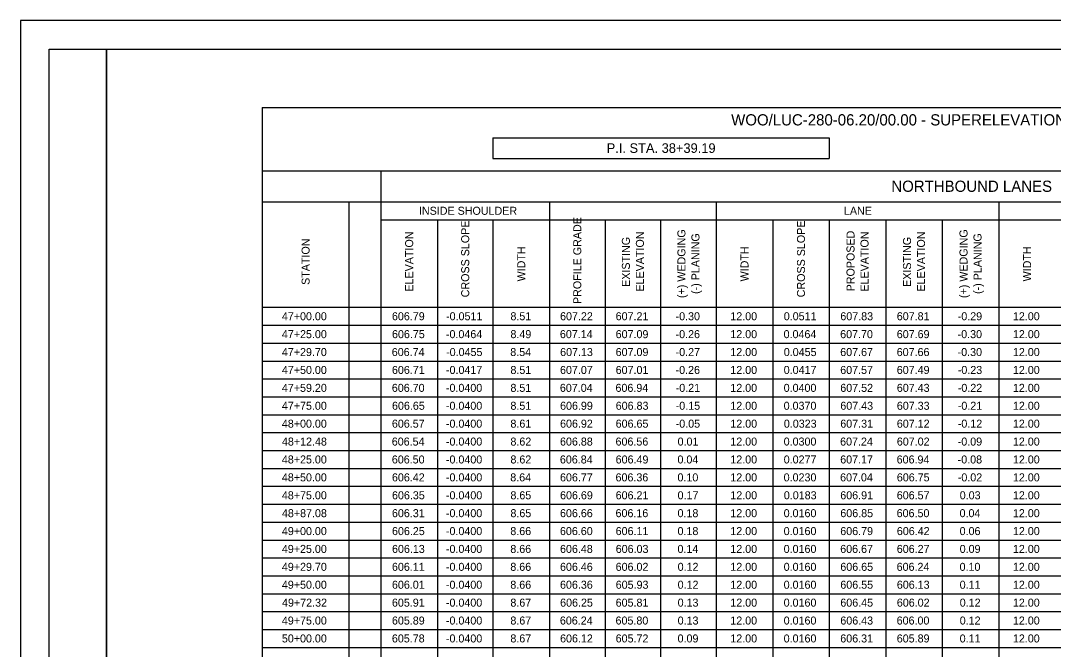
# Model space of a CAD drawing. Extents: x 0 to 34, y 0 to 22.
# Drawn here: x 0 to 18.06, y 11.01 to 22 of the extents above; entities that cross this region are included whole.
import ezdxf

# ---------------------------------------------------------------- set-up
doc = ezdxf.new("R2010")
doc.units = 0
for name, color, linetype in [('Default', 7, 'Continuous'), ('SH_Border', 7, 'Continuous'), ('SH_Cut_Line', 7, 'Continuous')]:
    doc.layers.add(name, color=color, linetype=linetype)

msp = doc.modelspace()

# ---------------------------------------------------------------- linework, layer by layer
at = {"layer": 'Default'}
for p, q in [((4.225, 20.48), (29.277, 20.48)), ((4.225, 20.48), (4.225, 1.522)), ((8.26, 19.953), (14.14, 19.953)), ((8.26, 19.953), (8.26, 19.591)), ((14.14, 19.953), (14.14, 19.591)), ((8.26, 19.591), (14.14, 19.591)), ((4.225, 19.376), (29.277, 19.376)), ((6.3, 19.376), (6.3, 1.522)), ((4.225, 18.833), (29.277, 18.833)), ((5.74, 18.833), (5.74, 1.522)), ((9.249, 18.833), (9.249, 1.522)), ((12.164, 18.833), (12.164, 1.522)), ((17.105, 18.833), (17.105, 1.522)), ((6.3, 18.52), (26.938, 18.52)), ((7.289, 18.52), (7.289, 1.522)), ((8.26, 18.52), (8.26, 1.522)), ((10.22, 18.52), (10.22, 1.522)), ((11.192, 18.52), (11.192, 1.522)), ((13.152, 18.52), (13.152, 1.522)), ((14.14, 18.52), (14.14, 1.522)), ((15.129, 18.52), (15.129, 1.522)), ((16.117, 18.52), (16.117, 1.522)), ((4.225, 16.988), (29.277, 16.988)), ((4.225, 16.675), (29.277, 16.675)), ((4.225, 16.362), (29.277, 16.362)), ((4.225, 16.049), (29.277, 16.049)), ((4.225, 15.736), (29.277, 15.736)), ((4.225, 15.424), (29.277, 15.424)), ((4.225, 15.111), (29.277, 15.111)), ((4.225, 14.798), (29.277, 14.798)), ((4.225, 14.485), (29.277, 14.485)), ((4.225, 14.172), (29.277, 14.172)), ((4.225, 13.859), (29.277, 13.859)), ((4.225, 13.546), (29.277, 13.546)), ((4.225, 13.233), (29.277, 13.233)), ((4.225, 12.92), (29.277, 12.92)), ((4.225, 12.607), (29.277, 12.607)), ((4.225, 12.294), (29.277, 12.294)), ((4.225, 11.981), (29.277, 11.981)), ((4.225, 11.668), (29.277, 11.668)), ((4.225, 11.355), (29.277, 11.355)), ((4.225, 11.042), (29.277, 11.042))]:
    msp.add_line(p, q, dxfattribs=at)
at = {"layer": 'SH_Border'}
for points in [[(0.5, 21.5), (1.5, 21.5), (1.5, 0.5), (0.5, 0.5)], [(1.5, 21.5), (33.5, 21.5), (33.5, 0.5), (1.5, 0.5)]]:
    msp.add_lwpolyline(points, close=True, dxfattribs=at)
at = {"layer": 'SH_Cut_Line'}
msp.add_lwpolyline([(0, 0), (34, 0), (34, 22), (0, 22)], close=True, dxfattribs=at)

# ---------------------------------------------------------------- texts
at = {"layer": 'Default'}
for s, height, p in [('WOO/LUC-280-06.20/00.00 - SUPERELEVATION TABLE', 0.196, (12.425, 20.168)), ('P.I. STA. 38+39.19', 0.168, (10.248, 19.688)), ('NORTHBOUND LANES', 0.196, (15.226, 19.007)), ('INSIDE SHOULDER', 0.14, (6.965, 18.606)), ('LANE', 0.14, (14.397, 18.606)), ('47+00.00', 0.14, (4.568, 16.762)), ('606.79', 0.14, (6.493, 16.762)), ('-0.0511', 0.14, (7.439, 16.762)), ('8.51', 0.14, (8.565, 16.762)), ('607.22', 0.14, (9.433, 16.762)), ('607.21', 0.14, (10.405, 16.762)), ('-0.30', 0.14, (11.453, 16.762)), ('12.00', 0.14, (12.41, 16.762)), ('0.0511', 0.14, (13.345, 16.762)), ('607.83', 0.14, (14.334, 16.762)), ('607.81', 0.14, (15.321, 16.762)), ('-0.29', 0.14, (16.387, 16.762)), ('12.00', 0.14, (17.352, 16.762)), ('47+25.00', 0.14, (4.568, 16.449)), ('606.75', 0.14, (6.494, 16.449)), ('-0.0464', 0.14, (7.437, 16.449)), ('8.49', 0.14, (8.565, 16.449)), ('607.14', 0.14, (9.43, 16.449)), ('607.09', 0.14, (10.405, 16.449)), ('-0.26', 0.14, (11.453, 16.449)), ('12.00', 0.14, (12.41, 16.449)), ('0.0464', 0.14, (13.342, 16.449)), ('607.70', 0.14, (14.331, 16.449)), ('607.69', 0.14, (15.321, 16.449)), ('-0.30', 0.14, (16.385, 16.449)), ('12.00', 0.14, (17.352, 16.449)), ('47+29.70', 0.14, (4.568, 16.136)), ('606.74', 0.14, (6.49, 16.136)), ('-0.0455', 0.14, (7.44, 16.136)), ('8.54', 0.14, (8.562, 16.136)), ('607.13', 0.14, (9.434, 16.136)), ('607.09', 0.14, (10.405, 16.136)), ('-0.27', 0.14, (11.454, 16.136)), ('12.00', 0.14, (12.41, 16.136)), ('0.0455', 0.14, (13.345, 16.136)), ('607.67', 0.14, (14.332, 16.136)), ('607.66', 0.14, (15.32, 16.136)), ('-0.30', 0.14, (16.385, 16.136)), ('12.00', 0.14, (17.352, 16.136)), ('47+50.00', 0.14, (4.568, 15.823)), ('606.71', 0.14, (6.493, 15.823)), ('-0.0417', 0.14, (7.438, 15.823)), ('8.51', 0.14, (8.565, 15.823)), ('607.07', 0.14, (9.432, 15.823)), ('607.01', 0.14, (10.405, 15.823)), ('-0.26', 0.14, (11.453, 15.823)), ('12.00', 0.14, (12.41, 15.823)), ('0.0417', 0.14, (13.344, 15.823)), ('607.57', 0.14, (14.332, 15.823)), ('607.49', 0.14, (15.321, 15.823)), ('-0.23', 0.14, (16.388, 15.823)), ('12.00', 0.14, (17.352, 15.823)), ('47+59.20', 0.14, (4.568, 15.51)), ('606.70', 0.14, (6.491, 15.51)), ('-0.0400', 0.14, (7.437, 15.51)), ('8.51', 0.14, (8.565, 15.51)), ('607.04', 0.14, (9.43, 15.51)), ('606.94', 0.14, (10.402, 15.51)), ('-0.21', 0.14, (11.455, 15.51)), ('12.00', 0.14, (12.41, 15.51)), ('0.0400', 0.14, (13.343, 15.51)), ('607.52', 0.14, (14.333, 15.51)), ('607.43', 0.14, (15.322, 15.51)), ('-0.22', 0.14, (16.388, 15.51)), ('12.00', 0.14, (17.352, 15.51)), ('47+75.00', 0.14, (4.568, 15.197)), ('606.65', 0.14, (6.494, 15.197)), ('-0.0400', 0.14, (7.437, 15.197)), ('8.51', 0.14, (8.565, 15.197)), ('606.99', 0.14, (9.433, 15.197)), ('606.83', 0.14, (10.406, 15.197)), ('-0.15', 0.14, (11.455, 15.197)), ('12.00', 0.14, (12.41, 15.197)), ('0.0370', 0.14, (13.343, 15.197)), ('607.43', 0.14, (14.334, 15.197)), ('607.33', 0.14, (15.322, 15.197)), ('-0.21', 0.14, (16.388, 15.197)), ('12.00', 0.14, (17.352, 15.197)), ('48+00.00', 0.14, (4.568, 14.884)), ('606.57', 0.14, (6.492, 14.884)), ('-0.0400', 0.14, (7.437, 14.884)), ('8.61', 0.14, (8.565, 14.884)), ('606.92', 0.14, (9.433, 14.884)), ('606.65', 0.14, (10.405, 14.884)), ('-0.05', 0.14, (11.455, 14.884)), ('12.00', 0.14, (12.41, 14.884)), ('0.0323', 0.14, (13.346, 14.884)), ('607.31', 0.14, (14.333, 14.884)), ('607.12', 0.14, (15.322, 14.884)), ('-0.12', 0.14, (16.388, 14.884)), ('12.00', 0.14, (17.352, 14.884)), ('48+12.48', 0.14, (4.569, 14.571)), ('606.54', 0.14, (6.49, 14.571)), ('-0.0400', 0.14, (7.437, 14.571)), ('8.62', 0.14, (8.565, 14.571)), ('606.88', 0.14, (9.432, 14.571)), ('606.56', 0.14, (10.403, 14.571)), ('0.01', 0.14, (11.488, 14.571)), ('12.00', 0.14, (12.41, 14.571)), ('0.0300', 0.14, (13.343, 14.571)), ('607.24', 0.14, (14.33, 14.571)), ('607.02', 0.14, (15.322, 14.571)), ('-0.09', 0.14, (16.387, 14.571)), ('12.00', 0.14, (17.352, 14.571)), ('48+25.00', 0.14, (4.568, 14.258)), ('606.50', 0.14, (6.491, 14.258)), ('-0.0400', 0.14, (7.437, 14.258)), ('8.62', 0.14, (8.565, 14.258)), ('606.84', 0.14, (9.43, 14.258)), ('606.49', 0.14, (10.405, 14.258)), ('0.04', 0.14, (11.486, 14.258)), ('12.00', 0.14, (12.41, 14.258)), ('0.0277', 0.14, (13.344, 14.258)), ('607.17', 0.14, (14.332, 14.258)), ('606.94', 0.14, (15.319, 14.258)), ('-0.08', 0.14, (16.386, 14.258)), ('12.00', 0.14, (17.352, 14.258)), ('48+50.00', 0.14, (4.568, 13.945)), ('606.42', 0.14, (6.493, 13.945)), ('-0.0400', 0.14, (7.437, 13.945)), ('8.64', 0.14, (8.562, 13.945)), ('606.77', 0.14, (9.432, 13.945)), ('606.36', 0.14, (10.403, 13.945)), ('0.10', 0.14, (11.486, 13.945)), ('12.00', 0.14, (12.41, 13.945)), ('0.0230', 0.14, (13.343, 13.945)), ('607.04', 0.14, (14.33, 13.945)), ('606.75', 0.14, (15.322, 13.945)), ('-0.02', 0.14, (16.388, 13.945)), ('12.00', 0.14, (17.352, 13.945)), ('48+75.00', 0.14, (4.568, 13.632)), ('606.35', 0.14, (6.494, 13.632)), ('-0.0400', 0.14, (7.437, 13.632)), ('8.65', 0.14, (8.565, 13.632)), ('606.69', 0.14, (9.433, 13.632)), ('606.21', 0.14, (10.405, 13.632)), ('0.17', 0.14, (11.488, 13.632)), ('12.00', 0.14, (12.41, 13.632)), ('0.0183', 0.14, (13.346, 13.632)), ('606.91', 0.14, (14.333, 13.632)), ('606.57', 0.14, (15.321, 13.632)), ('0.03', 0.14, (16.422, 13.632)), ('12.00', 0.14, (17.352, 13.632)), ('48+87.08', 0.14, (4.569, 13.319)), ('606.31', 0.14, (6.493, 13.319)), ('-0.0400', 0.14, (7.437, 13.319)), ('8.65', 0.14, (8.565, 13.319)), ('606.66', 0.14, (9.432, 13.319)), ('606.16', 0.14, (10.403, 13.319)), ('0.18', 0.14, (11.487, 13.319)), ('12.00', 0.14, (12.41, 13.319)), ('0.0160', 0.14, (13.343, 13.319)), ('606.85', 0.14, (14.334, 13.319)), ('606.50', 0.14, (15.319, 13.319)), ('0.04', 0.14, (16.419, 13.319)), ('12.00', 0.14, (17.352, 13.319)), ('49+00.00', 0.14, (4.568, 13.006)), ('606.25', 0.14, (6.494, 13.006)), ('-0.0400', 0.14, (7.437, 13.006)), ('8.66', 0.14, (8.563, 13.006)), ('606.60', 0.14, (9.431, 13.006)), ('606.11', 0.14, (10.405, 13.006)), ('0.18', 0.14, (11.487, 13.006)), ('12.00', 0.14, (12.41, 13.006)), ('0.0160', 0.14, (13.343, 13.006)), ('606.79', 0.14, (14.333, 13.006)), ('606.42', 0.14, (15.322, 13.006)), ('0.06', 0.14, (16.42, 13.006)), ('12.00', 0.14, (17.352, 13.006)), ('49+25.00', 0.14, (4.568, 12.694)), ('606.13', 0.14, (6.494, 12.694)), ('-0.0400', 0.14, (7.437, 12.694)), ('8.66', 0.14, (8.563, 12.694)), ('606.48', 0.14, (9.432, 12.694)), ('606.03', 0.14, (10.406, 12.694)), ('0.14', 0.14, (11.486, 12.694)), ('12.00', 0.14, (12.41, 12.694)), ('0.0160', 0.14, (13.343, 12.694)), ('606.67', 0.14, (14.332, 12.694)), ('606.27', 0.14, (15.321, 12.694)), ('0.09', 0.14, (16.421, 12.694)), ('12.00', 0.14, (17.352, 12.694)), ('49+29.70', 0.14, (4.568, 12.381)), ('606.11', 0.14, (6.493, 12.381)), ('-0.0400', 0.14, (7.437, 12.381)), ('8.66', 0.14, (8.563, 12.381)), ('606.46', 0.14, (9.432, 12.381)), ('606.02', 0.14, (10.405, 12.381)), ('0.12', 0.14, (11.489, 12.381)), ('12.00', 0.14, (12.41, 12.381)), ('0.0160', 0.14, (13.343, 12.381)), ('606.65', 0.14, (14.334, 12.381)), ('606.24', 0.14, (15.319, 12.381)), ('0.10', 0.14, (16.419, 12.381)), ('12.00', 0.14, (17.352, 12.381)), ('49+50.00', 0.14, (4.568, 12.068)), ('606.01', 0.14, (6.493, 12.068)), ('-0.0400', 0.14, (7.437, 12.068)), ('8.66', 0.14, (8.563, 12.068)), ('606.36', 0.14, (9.432, 12.068)), ('605.93', 0.14, (10.406, 12.068)), ('0.12', 0.14, (11.489, 12.068)), ('12.00', 0.14, (12.41, 12.068)), ('0.0160', 0.14, (13.343, 12.068)), ('606.55', 0.14, (14.334, 12.068)), ('606.13', 0.14, (15.322, 12.068)), ('0.11', 0.14, (16.421, 12.068)), ('12.00', 0.14, (17.352, 12.068)), ('49+72.32', 0.14, (4.571, 11.755)), ('605.91', 0.14, (6.493, 11.755)), ('-0.0400', 0.14, (7.437, 11.755)), ('8.67', 0.14, (8.564, 11.755)), ('606.25', 0.14, (9.434, 11.755)), ('605.81', 0.14, (10.405, 11.755)), ('0.13', 0.14, (11.489, 11.755)), ('12.00', 0.14, (12.41, 11.755)), ('0.0160', 0.14, (13.343, 11.755)), ('606.45', 0.14, (14.334, 11.755)), ('606.02', 0.14, (15.322, 11.755)), ('0.12', 0.14, (16.422, 11.755)), ('12.00', 0.14, (17.352, 11.755)), ('49+75.00', 0.14, (4.568, 11.442)), ('605.89', 0.14, (6.493, 11.442)), ('-0.0400', 0.14, (7.437, 11.442)), ('8.67', 0.14, (8.564, 11.442)), ('606.24', 0.14, (9.43, 11.442)), ('605.80', 0.14, (10.403, 11.442)), ('0.13', 0.14, (11.489, 11.442)), ('12.00', 0.14, (12.41, 11.442)), ('0.0160', 0.14, (13.343, 11.442)), ('606.43', 0.14, (14.334, 11.442)), ('606.00', 0.14, (15.319, 11.442)), ('0.12', 0.14, (16.422, 11.442)), ('12.00', 0.14, (17.352, 11.442)), ('50+00.00', 0.14, (4.568, 11.129)), ('605.78', 0.14, (6.492, 11.129)), ('-0.0400', 0.14, (7.437, 11.129)), ('8.67', 0.14, (8.564, 11.129)), ('606.12', 0.14, (9.433, 11.129)), ('605.72', 0.14, (10.405, 11.129)), ('0.09', 0.14, (11.488, 11.129)), ('12.00', 0.14, (12.41, 11.129)), ('0.0160', 0.14, (13.343, 11.129)), ('606.31', 0.14, (14.333, 11.129)), ('605.89', 0.14, (15.321, 11.129)), ('0.11', 0.14, (16.421, 11.129)), ('12.00', 0.14, (17.352, 11.129))]:
    msp.add_text(s, height=height, dxfattribs=at).set_placement(p)
for s, p in [('CROSS SLOPE', (7.844, 17.163)), ('PROFILE GRADE', (9.804, 17.046)), ('CROSS SLOPE', (13.716, 17.163)), ('ELEVATION', (6.864, 17.263)), ('ELEVATION', (10.899, 17.263)), ('(+) WEDGING', (11.625, 17.15)), ('(-) PLANING', (11.87, 17.222)), ('PROPOSED ', (14.582, 17.267)), ('ELEVATION', (14.827, 17.263)), ('ELEVATION', (15.815, 17.263)), ('(+) WEDGING', (16.558, 17.15)), ('(-) PLANING', (16.803, 17.222)), ('STATION', (5.053, 17.38)), ('EXISTING ', (10.654, 17.345)), ('EXISTING ', (15.57, 17.345)), ('WIDTH', (8.824, 17.441)), ('WIDTH', (12.728, 17.441)), ('WIDTH', (17.669, 17.441))]:
    msp.add_text(s, height=0.14, rotation=90, dxfattribs=at).set_placement(p)

doc.saveas('drawing.dxf')
